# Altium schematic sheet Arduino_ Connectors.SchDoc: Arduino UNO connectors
size A4; Date: 29-OCT-2015; Author: A.B; CompanyName: STMicroelectronics; Organization: MCD/TOOLS/GNB; Address1: 12, Rue Jules HOROWITZ; Address2: 38019 Grenoble; Address3: FRANCE; DocumentNumber: MB1225; Revision: B-01; SheetNumber: 7; SheetTotal: 12; Project: STM32F769I-DISCO
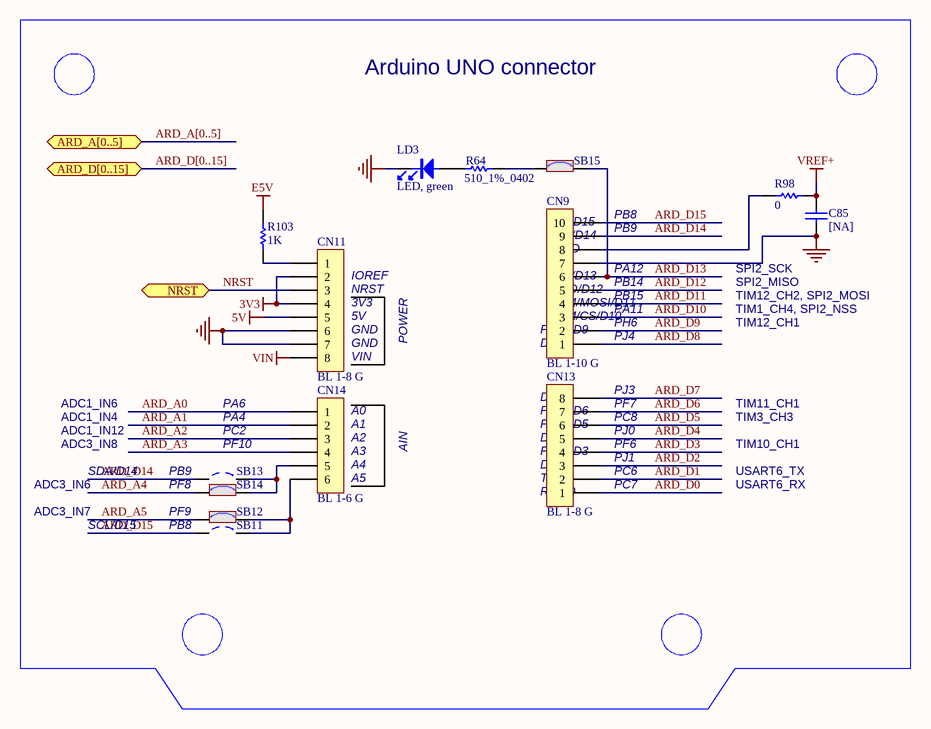
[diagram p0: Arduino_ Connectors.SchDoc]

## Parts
C85  [NA]  [0402C]
CN9  BL 1-10 G  [HDR_1X10_2R54_W]
CN11  BL 1-8 G  [HDR_1X8_2R54_W]
CN13  BL 1-8 G  [HDR_1X8_2R54_W]
CN14  BL 1-6 G  [HDR_1X6_2R54_W]
LD3  LED, green  [0603D]
R64  510_1%_0402  [0402R]
R98  0  [0402R]
R103  1K  [0402R]
SB11  Solder Bridge OFF  [JP2_SMD]  (value not drawn)
SB12  Solder Bridge ON  [JP2_SMD]  (value not drawn)
SB13  Solder Bridge OFF  [JP2_SMD]  (value not drawn)
SB14  Solder Bridge ON  [JP2_SMD]  (value not drawn)
SB15  Solder Bridge ON  [JP2_SMD]  (value not drawn)

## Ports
ARD_A[0..5], ARD_D[0..15], NRST

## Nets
3V3: CN11.2 CN11.4
5V: CN11.5
E5V: R103.2
GND: C85.1 CN9.7 CN11.6 CN11.7 LD3.2
VIN: CN11.8
VREF+: C85.2 R98.2
ARD_A0: CN14.1
ARD_A1: CN14.2
ARD_A2: CN14.3
ARD_A3: CN14.4
ARD_A4: SB14.1
ARD_A5: SB12.1
ARD_D0: CN13.1
ARD_D1: CN13.2
ARD_D2: CN13.3
ARD_D3: CN13.4
ARD_D4: CN13.5
ARD_D5: CN13.6
ARD_D6: CN13.7
ARD_D7: CN13.8
ARD_D8: CN9.1
ARD_D9: CN9.2
ARD_D10: CN9.3
ARD_D11: CN9.4
ARD_D12: CN9.5
ARD_D13: CN9.6 SB15.2
ARD_D14: CN9.9 SB13.1
ARD_D15: CN9.10 SB11.1
NRST: CN11.3 ; port NRST
NetCN9_8: CN9.8 R98.1
NetCN11_1: CN11.1 R103.1
NetCN14_5: CN14.5 SB13.2 SB14.2
NetCN14_6: CN14.6 SB11.2 SB12.2
NetLD3_1: LD3.1 R64.1
NetR64_2: R64.2 SB15.1

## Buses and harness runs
bus ARD_A[0..5] = port ARD_A[0..5]
bus ARD_D[0..15] = port ARD_D[0..15]

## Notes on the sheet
- Arduino UNO connector
- PB8
- (near CN11) IOREF
- (near CN11) NRST
- (near CN9) SDA/D14
- (near CN9) SCL/D15
- (near CN9) SCK/D13
- (near CN9) MISO/D12
- (near CN9) AVDD
- (near CN9) GND
- (near CN9) PB14
- (near CN9) PA12
- (near CN9) PB9
- SPI2_MISO
- SPI2_SCK
- (near CN11) 3V3
- (near CN11) 5V
- (near CN11) GND
- POWER
- (near CN9) D8
- (near CN9) PWM/D9
- (near CN9) PWM/CS/D10
- (near CN9) PWM/MOSI/D11
- (near CN9) PA11
- (near CN9) PJ4
- (near CN9) PH6
- (near CN9) PB15
- TIM12_CH1
- TIM1_CH4, SPI2_NSS
- TIM12_CH2, SPI2_MOSI
- ADC1_IN4
- ADC1_IN6
- PA6
- PA4
- (near CN14) A0
- (near CN14) A1
- (near CN11) VIN
- (near CN13) PWM/D5
- (near CN13) PWM/D6
- (near CN13) D7
- (near CN13) PF7
- PJ3
- (near CN13) PC8
- TIM3_CH3
- TIM11_CH1
- ADC3_IN6
- ADC3_IN8
- ADC1_IN12
- SDA/D14
- PB9
- PF8
- PC2
- PF10
- (near CN14) A2
- (near CN14) A3
- (near CN14) A4
- (near CN14) A5
- AIN
- (near CN13) TX/D1
- (near CN13) D2
- (near CN13) D4
- (near CN13) PWM/D3
- (near CN13) PC6
- (near CN13) PJ1
- (near CN13) PF6
- (near CN13) PJ0
- (near CN13) PC7
- USART6_RX
- USART6_TX
- TIM10_CH1
- ADC3_IN7
- SCL/D15
- PF9
- (near CN13) RX/D0

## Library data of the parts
C85 = Cap_NA_0402: Capacitor,NA,0402; Fitted: NO
CN9 = Header 10X1_Female_THT: Header, 10-Pin, Single row, female, THT, 2.54; Manuf_1: Fischer Electronik
CN11 CN13 = Header 8X1_Female_THT: Header, 8-Pins, Single row, female, THT, 2.54; Manuf_1: Fischer Electronik
CN14 = Header 6X1_Female_THT: Header, 6-Pins, Single row, female THT, 2.54; Manuf_1: Fischer Electronik
LD3 = LED_green: LED, green, 0603; Manuf_1: everlight; Manuf_Part_1: 19-213SYGC/S530-E2/TR8; Description: LED,green,0603,19-213SYGC/S530-E2/TR8,everlight; ECCN_US/EU: EAR99/NEC
R64 = Res_510_1%_0402: Resistor,510,0402,1%,YAGEO; Manuf_Part_1: RC0402FR-07510L; Value: 510
R98 = Res_0_5%_0402: Resistor,0,0402,5%,YAGEO; Manuf_Part_1: RC0402JR-070RL; Order: 2363467
R103 = Res_1K_1%_0402: Resistor,1K,0402,1%,YAGEO; Manuf_Part_1: RC0402FR-071KL
SB11 SB13 = SB_OFF: Solder: NO
SB12 SB14 SB15 = SB_ON: Solder: YES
